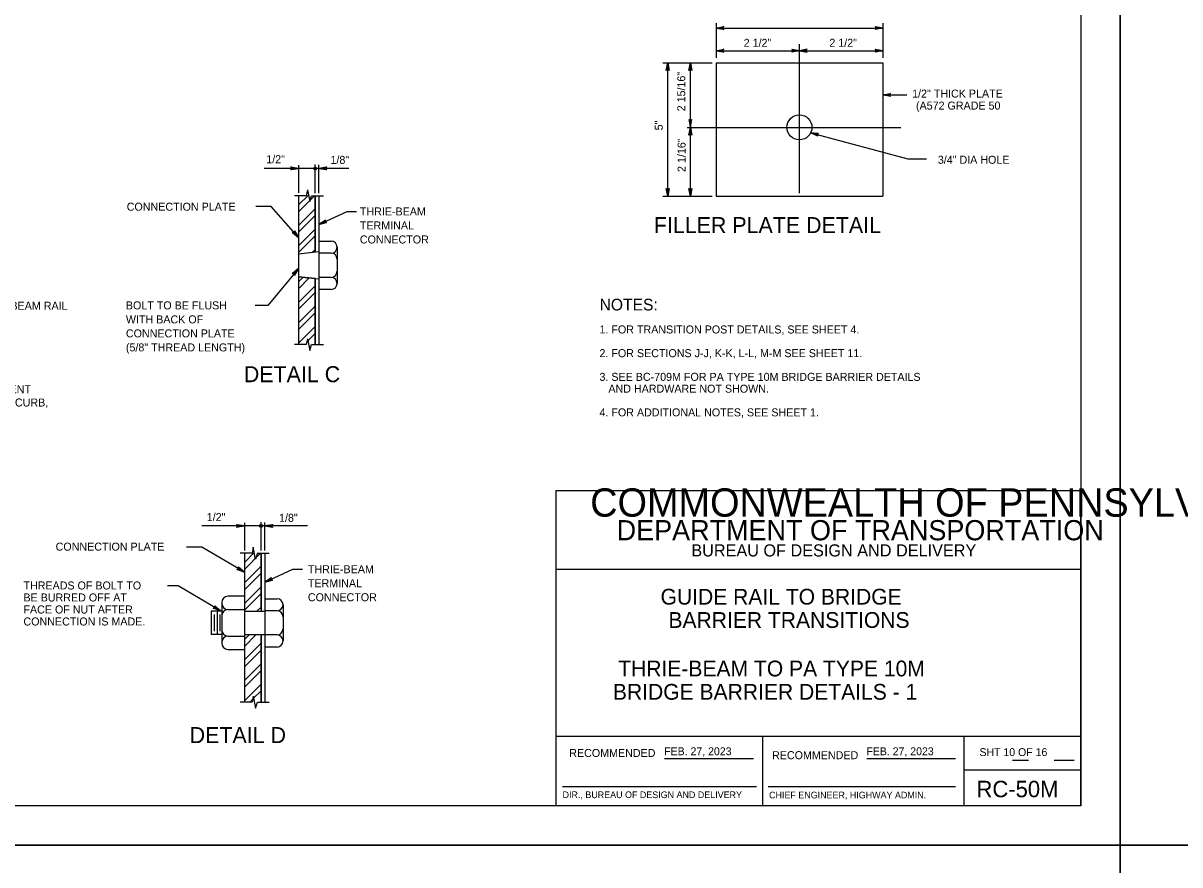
# Model space of a CAD drawing. Extents: x 632007860 to 635435983, y 295418622 to 297794622.
# Drawn here: x 634113016 to 634553598, y 296599122 to 296919777 of the extents above; entities that cross this region are included whole.
import ezdxf

# ---------------------------------------------------------------- set-up
doc = ezdxf.new("R2010")
doc.units = 0
for name, color, linetype in [('1', 7, 'Continuous'), ('2', 7, 'Continuous'), ('8', 7, 'Continuous'), ('PLT-BNDY', 7, 'Continuous'), ('S-DETL-DIMS', 7, 'Continuous'), ('S-DETL-T120', 7, 'Continuous'), ('S-DETL-T175', 7, 'Continuous'), ('S-DETL-T240', 7, 'Continuous'), ('S-PATT-WT01', 7, 'Continuous'), ('S-STEL', 7, 'Continuous')]:
    doc.layers.add(name, color=color, linetype=linetype)

msp = doc.modelspace()

# ---------------------------------------------------------------- linework, layer by layer
at = {"layer": '1'}
for p, q in [((634515860, 297185622), (634515860, 296621622)), ((634515860, 296741622), (634315860, 296741622)), ((634315860, 296741622), (634315860, 296621622)), ((634515860, 296621622), (634515860, 296741622)), ((634515860, 296711622), (634315860, 296711622)), ((634515860, 296647981), (634315860, 296647981)), ((634394661, 296647981), (634394661, 296621622)), ((634471362, 296647981), (634471362, 296621622)), ((634357325, 296639611), (634391211, 296639611)), ((634434323, 296639611), (634468193, 296639611)), ((634489803, 296638991), (634495945, 296638991)), ((634505683, 296638991), (634513329, 296638991)), ((634471362, 296635300), (634515860, 296635300)), ((634318485, 296628918), (634392385, 296628918)), ((634396791, 296628918), (634468131, 296628918)), ((634515860, 296621622), (633729860, 296621622))]:
    msp.add_line(p, q, dxfattribs=at)
at = {"layer": '8'}
for p, q in [((634408710, 296854982), (634408710, 296911744)), ((634365884, 296880076), (634447316, 296880076)), ((634224238, 296854043), (634224238, 296832606)), ((634224238, 296822469), (634224238, 296797306))]:
    msp.add_line(p, q, dxfattribs=at)
at = {"layer": 'PLT-BNDY'}
for points in [[(633689860, 297200622), (634530860, 297200622), (634530860, 296606622), (633689860, 296606622)], [(634530860, 297200622), (635371860, 297200622), (635371860, 296606622), (634530860, 296606622)], [(633689860, 296606622), (634530860, 296606622), (634530860, 296012622), (633689860, 296012622)], [(634530860, 296606622), (635371860, 296606622), (635371860, 296012622), (634530860, 296012622)]]:
    msp.add_lwpolyline(points, close=True, dxfattribs=at)
at = {"layer": 'S-DETL-DIMS'}
for p, q in [((634376959, 296919777), (634376959, 296906595)), ((634376959, 296917916), (634440460, 296917916)), ((634440460, 296919777), (634440460, 296906595)), ((634376959, 296909283), (634440460, 296909283)), ((634356686, 296904689), (634375430, 296904689)), ((634358547, 296853878), (634358547, 296904689)), ((634367180, 296853878), (634367180, 296904689)), ((634440460, 296892421), (634449661, 296892421)), ((634412998, 296878006), (634450005, 296868034)), ((634225704, 296864448), (634204882, 296864448)), ((634217882, 296865684), (634217882, 296855108)), ((634224238, 296855042), (634224238, 296865884)), ((634225704, 296855042), (634225704, 296865817)), ((634237068, 296864448), (634225704, 296864448)), ((634450005, 296868034), (634457063, 296868034)), ((634221271, 296856305), (634220807, 296854043)), ((634221271, 296856305), (634222171, 296851776)), ((634220807, 296854043), (634216318, 296854043)), ((634222171, 296851776), (634222851, 296854043)), ((634222851, 296854043), (634227378, 296854043)), ((634356686, 296853878), (634375430, 296853878)), ((634221271, 296799568), (634220807, 296797306)), ((634221271, 296799568), (634222171, 296795039)), ((634220807, 296797306), (634216318, 296797306)), ((634222171, 296795039), (634222851, 296797306)), ((634222851, 296797306), (634227378, 296797306)), ((634205098, 296728229), (634181069, 296728229)), ((634197277, 296729465), (634197277, 296718889)), ((634203632, 296718823), (634203632, 296729665)), ((634205098, 296718823), (634205098, 296729598)), ((634221315, 296728229), (634205098, 296728229)), ((634200665, 296720086), (634200202, 296717824)), ((634201565, 296715557), (634200665, 296720086)), ((634200202, 296717824), (634195712, 296717824)), ((634202245, 296717824), (634201565, 296715557)), ((634202245, 296717824), (634206772, 296717824)), ((634200665, 296663349), (634200202, 296661087)), ((634200665, 296663349), (634201565, 296658820)), ((634200202, 296661087), (634195712, 296661087)), ((634201565, 296658820), (634202245, 296661087)), ((634202245, 296661087), (634206772, 296661087))]:
    msp.add_line(p, q, dxfattribs=at)
for points in [[(634376959, 296917916), (634379919, 296918470), (634379690, 296918312), (634379573, 296918114), (634379539, 296917916), (634379573, 296917717), (634379690, 296917519), (634379919, 296917361), (634376959, 296917916), (634379690, 296917519), (634379573, 296917717), (634376959, 296917916), (634379539, 296917916), (634379573, 296918114), (634376959, 296917916), (634379690, 296918312)], [(634440460, 296917916), (634437501, 296917361), (634437729, 296917519), (634437846, 296917717), (634437880, 296917916), (634437846, 296918114), (634437729, 296918312), (634437501, 296918470), (634440460, 296917916), (634437729, 296918312), (634437846, 296918114), (634440460, 296917916), (634437880, 296917916), (634437846, 296917717), (634440460, 296917916), (634437729, 296917519)], [(634376959, 296909283), (634379919, 296909837), (634379690, 296909679), (634379573, 296909481), (634379539, 296909283), (634379573, 296909084), (634379690, 296908886), (634379919, 296908728), (634376959, 296909283), (634379690, 296908886), (634379573, 296909084), (634376959, 296909283), (634379539, 296909283), (634379573, 296909481), (634376959, 296909283), (634379690, 296909679)], [(634408710, 296909283), (634405750, 296908728), (634405978, 296908886), (634406096, 296909084), (634406130, 296909283), (634406096, 296909481), (634405978, 296909679), (634405750, 296909837), (634408710, 296909283), (634405978, 296909679), (634406096, 296909481), (634408710, 296909283), (634406130, 296909283), (634406096, 296909084), (634408710, 296909283), (634405978, 296908886)], [(634408710, 296909283), (634411669, 296908728), (634411441, 296908886), (634411323, 296909084), (634411289, 296909283), (634411323, 296909481), (634411441, 296909679), (634411669, 296909837), (634408710, 296909283), (634411441, 296909679), (634411323, 296909481), (634408710, 296909283), (634411289, 296909283), (634411323, 296909084), (634408710, 296909283), (634411441, 296908886)], [(634440460, 296909283), (634437501, 296908728), (634437729, 296908886), (634437846, 296909084), (634437880, 296909283), (634437846, 296909481), (634437729, 296909679), (634437501, 296909837), (634440460, 296909283), (634437729, 296909679), (634437846, 296909481), (634440460, 296909283), (634437880, 296909283), (634437846, 296909084), (634440460, 296909283), (634437729, 296908886)], [(634358547, 296904689), (634359102, 296901729), (634358944, 296901957), (634358746, 296902075), (634358547, 296902109), (634358349, 296902075), (634358150, 296901957), (634357992, 296901729), (634358547, 296904689), (634358150, 296901957), (634358349, 296902075), (634358547, 296904689), (634358547, 296902109), (634358746, 296902075), (634358547, 296904689), (634358944, 296901957)], [(634367180, 296904689), (634367735, 296901729), (634367577, 296901957), (634367379, 296902075), (634367180, 296902109), (634366982, 296902075), (634366783, 296901957), (634366625, 296901729), (634367180, 296904689), (634366783, 296901957), (634366982, 296902075), (634367180, 296904689), (634367180, 296902109), (634367379, 296902075), (634367180, 296904689), (634367577, 296901957)], [(634440460, 296892421), (634443419, 296892976), (634443191, 296892818), (634443074, 296892619), (634443040, 296892421), (634443074, 296892222), (634443191, 296892024), (634443419, 296891866), (634440460, 296892421), (634443191, 296892024), (634443074, 296892222), (634440460, 296892421), (634443040, 296892421), (634443074, 296892619), (634440460, 296892421), (634443191, 296892818)], [(634367180, 296880076), (634367735, 296883035), (634367577, 296882807), (634367379, 296882690), (634367180, 296882656), (634366982, 296882690), (634366783, 296882807), (634366625, 296883035), (634367180, 296880076), (634366783, 296882807), (634366982, 296882690), (634367180, 296880076), (634367180, 296882656), (634367379, 296882690), (634367180, 296880076), (634367577, 296882807)], [(634367180, 296880076), (634367735, 296877117), (634367577, 296877345), (634367379, 296877462), (634367180, 296877496), (634366982, 296877462), (634366783, 296877345), (634366625, 296877117), (634367180, 296880076), (634366783, 296877345), (634366982, 296877462), (634367180, 296880076), (634367180, 296877496), (634367379, 296877462), (634367180, 296880076), (634367577, 296877345)], [(634412998, 296878006), (634416000, 296877771), (634415870, 296877725), (634415739, 296877678), (634415656, 296877598), (634415574, 296877517), (634415531, 296877426), (634415489, 296877334), (634415480, 296877234), (634415470, 296877134), (634415501, 296877023), (634415532, 296876912), (634415622, 296876806), (634415711, 296876700), (634412998, 296878006), (634415622, 296876806), (634415532, 296876912), (634412998, 296878006), (634415501, 296877023), (634415470, 296877134), (634412998, 296878006), (634415480, 296877234), (634415489, 296877334), (634412998, 296878006), (634415531, 296877426), (634415574, 296877517), (634412998, 296878006), (634415656, 296877598), (634415739, 296877678), (634412998, 296878006), (634415870, 296877725)], [(634217882, 296864448), (634214923, 296863893), (634215037, 296863972), (634215151, 296864051), (634215210, 296864151), (634215269, 296864250), (634215286, 296864349), (634215303, 296864448), (634215286, 296864547), (634215269, 296864647), (634215210, 296864746), (634215151, 296864845), (634215037, 296864924), (634214923, 296865003), (634217882, 296864448), (634215037, 296864924), (634215151, 296864845), (634217882, 296864448), (634215210, 296864746), (634215269, 296864647), (634217882, 296864448), (634215286, 296864547), (634215303, 296864448), (634217882, 296864448), (634215286, 296864349), (634215269, 296864250), (634217882, 296864448), (634215210, 296864151), (634215151, 296864051), (634217882, 296864448), (634215037, 296863972)], [(634225704, 296864448), (634228663, 296865003), (634228549, 296864924), (634228435, 296864845), (634228377, 296864746), (634228318, 296864647), (634228301, 296864547), (634228284, 296864448), (634228301, 296864349), (634228318, 296864250), (634228377, 296864151), (634228435, 296864051), (634228549, 296863972), (634228663, 296863893), (634225704, 296864448), (634228549, 296863972), (634228435, 296864051), (634225704, 296864448), (634228377, 296864151), (634228318, 296864250), (634225704, 296864448), (634228301, 296864349), (634228284, 296864448), (634225704, 296864448), (634228301, 296864547), (634228318, 296864647), (634225704, 296864448), (634228377, 296864746), (634228435, 296864845), (634225704, 296864448), (634228549, 296864924)], [(634358547, 296853878), (634357992, 296856837), (634358150, 296856609), (634358349, 296856492), (634358547, 296856458), (634358746, 296856492), (634358944, 296856609), (634359102, 296856837), (634358547, 296853878), (634358944, 296856609), (634358746, 296856492), (634358547, 296853878), (634358547, 296856458), (634358349, 296856492), (634358547, 296853878), (634358150, 296856609)], [(634367180, 296853878), (634366625, 296856837), (634366783, 296856609), (634366982, 296856492), (634367180, 296856458), (634367379, 296856492), (634367577, 296856609), (634367735, 296856837), (634367180, 296853878), (634367577, 296856609), (634367379, 296856492), (634367180, 296853878), (634367180, 296856458), (634366982, 296856492), (634367180, 296853878), (634366783, 296856609)], [(634217882, 296838130), (634207457, 296849897), (634201605, 296849897)], [(634225704, 296843087), (634236381, 296848043), (634239983, 296848043)], [(634225704, 296843087), (634228155, 296844836), (634228084, 296844716), (634228014, 296844597), (634228003, 296844482), (634227991, 296844367), (634228017, 296844270), (634228044, 296844173), (634228101, 296844090), (634228158, 296844007), (634228253, 296843942), (634228348, 296843877), (634228485, 296843853), (634228622, 296843829), (634225704, 296843087), (634228485, 296843853), (634228348, 296843877), (634225704, 296843087), (634228253, 296843942), (634228158, 296844007), (634225704, 296843087), (634228101, 296844090), (634228044, 296844173), (634225704, 296843087), (634228017, 296844270), (634227991, 296844367), (634225704, 296843087), (634228003, 296844482), (634228014, 296844597), (634225704, 296843087), (634228084, 296844716)], [(634217882, 296838130), (634215505, 296839977), (634215639, 296839944), (634215774, 296839911), (634215887, 296839933), (634216001, 296839955), (634216086, 296840008), (634216172, 296840061), (634216235, 296840139), (634216298, 296840218), (634216333, 296840328), (634216368, 296840437), (634216352, 296840575), (634216335, 296840713), (634217882, 296838130), (634216352, 296840575), (634216368, 296840437), (634217882, 296838130), (634216333, 296840328), (634216298, 296840218), (634217882, 296838130), (634216235, 296840139), (634216172, 296840061), (634217882, 296838130), (634216086, 296840008), (634216001, 296839955), (634217882, 296838130), (634215887, 296839933), (634215774, 296839911), (634217882, 296838130), (634215639, 296839944)], [(634217882, 296826245), (634206216, 296812202), (634201444, 296812202)], [(634217882, 296826245), (634216371, 296823641), (634216386, 296823779), (634216400, 296823917), (634216364, 296824026), (634216327, 296824135), (634216263, 296824213), (634216199, 296824291), (634216112, 296824343), (634216026, 296824394), (634215913, 296824415), (634215799, 296824435), (634215665, 296824400), (634215531, 296824365), (634217882, 296826245), (634215665, 296824400), (634215799, 296824435), (634217882, 296826245), (634215913, 296824415), (634216026, 296824394), (634217882, 296826245), (634216112, 296824343), (634216199, 296824291), (634217882, 296826245), (634216263, 296824213), (634216327, 296824135), (634217882, 296826245), (634216364, 296824026), (634216400, 296823917), (634217882, 296826245), (634216386, 296823779)], [(634197277, 296728229), (634194317, 296727674), (634194431, 296727753), (634194545, 296727832), (634194604, 296727932), (634194663, 296728031), (634194680, 296728130), (634194697, 296728229), (634194680, 296728328), (634194663, 296728428), (634194604, 296728527), (634194545, 296728626), (634194431, 296728705), (634194317, 296728784), (634197277, 296728229), (634194431, 296728705), (634194545, 296728626), (634197277, 296728229), (634194604, 296728527), (634194663, 296728428), (634197277, 296728229), (634194680, 296728328), (634194697, 296728229), (634197277, 296728229), (634194680, 296728130), (634194663, 296728031), (634197277, 296728229), (634194604, 296727932), (634194545, 296727832), (634197277, 296728229), (634194431, 296727753)], [(634205098, 296728229), (634208058, 296728784), (634207944, 296728705), (634207830, 296728626), (634207771, 296728527), (634207712, 296728428), (634207695, 296728328), (634207678, 296728229), (634207695, 296728130), (634207712, 296728031), (634207771, 296727932), (634207830, 296727832), (634207944, 296727753), (634208058, 296727674), (634205098, 296728229), (634207944, 296727753), (634207830, 296727832), (634205098, 296728229), (634207771, 296727932), (634207712, 296728031), (634205098, 296728229), (634207695, 296728130), (634207678, 296728229), (634205098, 296728229), (634207695, 296728328), (634207712, 296728428), (634205098, 296728229), (634207771, 296728527), (634207830, 296728626), (634205098, 296728229), (634207944, 296728705)], [(634197277, 296710652), (634181108, 296720161), (634175255, 296720161)], [(634197277, 296710652), (634194444, 296711674), (634194583, 296711685), (634194721, 296711695), (634194822, 296711751), (634194923, 296711806), (634194988, 296711883), (634195053, 296711960), (634195089, 296712054), (634195124, 296712148), (634195124, 296712264), (634195123, 296712379), (634195065, 296712505), (634195007, 296712631), (634197277, 296710652), (634195065, 296712505), (634195123, 296712379), (634197277, 296710652), (634195124, 296712264), (634195124, 296712148), (634197277, 296710652), (634195089, 296712054), (634195053, 296711960), (634197277, 296710652), (634194988, 296711883), (634194923, 296711806), (634197277, 296710652), (634194822, 296711751), (634194721, 296711695), (634197277, 296710652), (634194583, 296711685)], [(634205098, 296706868), (634215775, 296711825), (634219377, 296711825)], [(634205098, 296706868), (634207549, 296708617), (634207478, 296708497), (634207408, 296708378), (634207397, 296708263), (634207385, 296708148), (634207412, 296708051), (634207438, 296707954), (634207495, 296707871), (634207552, 296707788), (634207647, 296707723), (634207743, 296707658), (634207879, 296707634), (634208016, 296707611), (634205098, 296706868), (634207879, 296707634), (634207743, 296707658), (634205098, 296706868), (634207647, 296707723), (634207552, 296707788), (634205098, 296706868), (634207495, 296707871), (634207438, 296707954), (634205098, 296706868), (634207412, 296708051), (634207385, 296708148), (634205098, 296706868), (634207397, 296708263), (634207408, 296708378), (634205098, 296706868), (634207478, 296708497)], [(634188252, 296695858), (634172083, 296705367), (634168035, 296705367)], [(634188252, 296695858), (634185420, 296696880), (634185558, 296696890), (634185696, 296696900), (634185797, 296696956), (634185898, 296697012), (634185963, 296697089), (634186028, 296697166), (634186064, 296697260), (634186099, 296697354), (634186099, 296697469), (634186099, 296697585), (634186041, 296697711), (634185982, 296697836), (634188252, 296695858), (634186041, 296697711), (634186099, 296697585), (634188252, 296695858), (634186099, 296697469), (634186099, 296697354), (634188252, 296695858), (634186064, 296697260), (634186028, 296697166), (634188252, 296695858), (634185963, 296697089), (634185898, 296697012), (634188252, 296695858), (634185797, 296696956), (634185696, 296696900), (634188252, 296695858), (634185558, 296696890)]]:
    msp.add_lwpolyline(points, dxfattribs=at)
for centre, radius in [((634224238, 296864448), 529), ((634224238, 296864448), 265), ((634203632, 296728229), 529), ((634203632, 296728229), 265)]:
    msp.add_circle(centre, radius, dxfattribs=at)
at = {"layer": 'S-PATT-WT01'}
for p, q in [((634217882, 296850513), (634221670, 296854300)), ((634217882, 296847920), (634224005, 296854043)), ((634217882, 296842735), (634224238, 296849090)), ((634217882, 296840143), (634224238, 296846498)), ((634217882, 296834958), (634224238, 296841313)), ((634217882, 296832365), (634224238, 296838720)), ((634223199, 296832497), (634224238, 296833535)), ((634217882, 296821169), (634219663, 296822950)), ((634217882, 296818577), (634222009, 296822703)), ((634217882, 296813392), (634224238, 296819747)), ((634217882, 296810799), (634224238, 296817154)), ((634217882, 296805614), (634224238, 296811969)), ((634217882, 296803022), (634224238, 296809377)), ((634217882, 296797837), (634224238, 296804192)), ((634221426, 296798788), (634224238, 296801599)), ((634197277, 296714294), (634201064, 296718081)), ((634197277, 296711701), (634203399, 296717824)), ((634197277, 296706516), (634203632, 296712871)), ((634197277, 296703924), (634203632, 296710279)), ((634197277, 296698738), (634203632, 296705094)), ((634197277, 296696146), (634203632, 296702501)), ((634202034, 296695718), (634203632, 296697316)), ((634197277, 296684950), (634199245, 296686918)), ((634197277, 296682358), (634201837, 296686918)), ((634197277, 296677173), (634203632, 296683528)), ((634197277, 296674580), (634203632, 296680935)), ((634197277, 296669395), (634203632, 296675750)), ((634197277, 296666803), (634203632, 296673158)), ((634197277, 296661618), (634203632, 296667973)), ((634199339, 296661087), (634200424, 296662173)), ((634200820, 296662569), (634203632, 296665380))]:
    msp.add_line(p, q, dxfattribs=at)
at = {"layer": 'S-STEL'}
for p, q in [((634376959, 296904689), (634440460, 296904689)), ((634376959, 296904689), (634376959, 296853878)), ((634440460, 296904689), (634440460, 296853878)), ((634217882, 296854043), (634217882, 296797306)), ((634217882, 296854043), (634217882, 296831937)), ((634224238, 296832606), (634224238, 296854043)), ((634225704, 296854043), (634225704, 296832760)), ((634376959, 296853878), (634440460, 296853878)), ((634225704, 296836745), (634225704, 296818329)), ((634225704, 296836745), (634225704, 296836745)), ((634225704, 296836745), (634230315, 296836745)), ((634232613, 296834447), (634232613, 296820628)), ((634217882, 296831937), (634225704, 296832760)), ((634217882, 296831937), (634224238, 296832606)), ((634230315, 296832141), (634225704, 296832141)), ((634217882, 296823138), (634225704, 296822314)), ((634224238, 296822469), (634217882, 296823138)), ((634217882, 296823138), (634217882, 296797306)), ((634224238, 296797306), (634224238, 296822469)), ((634230315, 296822933), (634225704, 296822933)), ((634225704, 296822314), (634225704, 296797306)), ((634225704, 296818329), (634225704, 296818329)), ((634230315, 296818329), (634225704, 296818329)), ((634197277, 296717824), (634197277, 296661087)), ((634197277, 296717824), (634197277, 296695718)), ((634203632, 296717824), (634203632, 296695718)), ((634203632, 296696387), (634203632, 296717824)), ((634205098, 296717824), (634205098, 296695718)), ((634197277, 296701447), (634190999, 296701447)), ((634188701, 296698919), (634188701, 296683718)), ((634205098, 296700526), (634205098, 296682110)), ((634205098, 296700526), (634205098, 296700526)), ((634205098, 296700526), (634209710, 296700526)), ((634212008, 296698228), (634212008, 296684409)), ((634188701, 296695718), (634184688, 296695718)), ((634184688, 296695718), (634184688, 296686918)), ((634185779, 296694511), (634185779, 296688118)), ((634186871, 296695710), (634186871, 296686918)), ((634187962, 296694511), (634187962, 296688118)), ((634190999, 296696382), (634197277, 296696382)), ((634197277, 296695718), (634205098, 296695718)), ((634209710, 296695922), (634205098, 296695922)), ((634188701, 296686918), (634184688, 296686918)), ((634190999, 296686254), (634197277, 296686254)), ((634197277, 296686918), (634205098, 296686918)), ((634197277, 296686918), (634197277, 296661087)), ((634203632, 296686918), (634203632, 296661087)), ((634203632, 296661087), (634203632, 296686250)), ((634205098, 296686918), (634205098, 296661087)), ((634209710, 296686714), (634205098, 296686714)), ((634190999, 296681189), (634197277, 296681189)), ((634205098, 296682110), (634205098, 296682110)), ((634209710, 296682110), (634205098, 296682110))]:
    msp.add_line(p, q, dxfattribs=at)
msp.add_circle((634408710, 296880076), 4763, dxfattribs=at)
for centre, start, end in [((634230315, 296834447), 0, 90), ((634230315, 296834439), 270, 0), ((634230315, 296829843), 0, 90), ((634230315, 296825232), 270, 0), ((634230315, 296820635), 0, 90), ((634230315, 296820628), 270, 0), ((634209710, 296698228), 0, 90), ((634209710, 296698220), 270, 0), ((634209710, 296693624), 0, 90), ((634209710, 296689013), 270, 0), ((634209710, 296684416), 0, 90), ((634209710, 296684409), 270, 0)]:
    msp.add_arc(centre, 2298, start, end, dxfattribs=at)
for centre, start_param, end_param in [((634190999, 296698919), 3.1415927, 4.712389), ((634190999, 296698911), 4.712389, 6.2831853), ((634190999, 296693854), 3.1415927, 4.712389), ((634190999, 296688782), 4.712389, 6.2831853), ((634190999, 296683726), 3.1415927, 4.712389), ((634190999, 296683718), 4.712389, 6.2831853)]:
    msp.add_ellipse(centre, major_axis=(0, -2528), ratio=0.9090909, start_param=start_param, end_param=end_param, dxfattribs=at)

# ---------------------------------------------------------------- texts
at = {"layer": '1'}
for s, height, p in [('COMMONWEALTH OF PENNSYLVANIA', 10783.37, (634329011, 296731766)), ('DEPARTMENT OF TRANSPORTATION', 7684.29, (634339072, 296722771)), ('BUREAU OF DESIGN AND DELIVERY', 4622.09, (634367520, 296716609)), ('RECOMMENDED', 3048, (634321023, 296640216)), ('FEB. 27, 2023', 3000, (634357186, 296640887)), ('RECOMMENDED', 3048, (634398267, 296639379)), ('FEB. 27, 2023', 3000, (634434184, 296640887)), ('SHT 10 OF 16', 3000, (634477259, 296640576)), ('APPROVED', 19.2, (634358883, 296639554)), ('RC-50M', 6267.5, (634476143, 296624882)), ('DIR., BUREAU OF DESIGN AND DELIVERY', 2540, (634318485, 296624554)), ('CHIEF ENGINEER, HIGHWAY ADMIN.', 2540, (634397144, 296624445))]:
    msp.add_text(s, height=height, dxfattribs=at).set_placement(p)
at = {"layer": '2'}
for s, p in [('GUIDE RAIL TO BRIDGE', (634355804, 296698276)), ('BARRIER TRANSITIONS', (634358804, 296689401)), ('THRIE-BEAM TO PA TYPE 10M', (634339665, 296670927)), ('BRIDGE BARRIER DETAILS - 1', (634337657, 296662044))]:
    msp.add_text(s, height=6000, dxfattribs=at).set_placement(p)
at = {"layer": 'S-DETL-T120'}
for s, height, p in [('2 1/2"', 3048.1, (634387460, 296910748)), ('2 1/2"', 3048.1, (634420093, 296910771)), ('1/2" THICK PLATE', 3048, (634451629, 296891411)), ('(A572 GRADE 50', 3048, (634453093, 296886839)), (' 1/2"', 3048, (634204489, 296866410)), (' 1/8"', 3048, (634228949, 296866167)), ('3/4" DIA HOLE', 3048, (634461419, 296866203)), ('CONNECTION PLATE', 3048.01, (634152471, 296848319)), ('THRIE-BEAM ', 3048.01, (634241272, 296846511)), ('TERMINAL', 3048, (634241272, 296841177)), ('CONNECTOR', 3048, (634241272, 296835843)), ('   THRIE-BEAM RAIL', 3048.01, (634091212, 296810592)), ('BOLT TO BE FLUSH', 3048.01, (634152155, 296810728)), ('WITH BACK OF ', 3048.01, (634152155, 296805394)), ('CONNECTION PLATE', 3048.01, (634152155, 296800060)), ('(5/8" THREAD LENGTH)', 3048.01, (634152155, 296794726)), ('PLAIN CEMENT', 3048.01, (634085884, 296778813)), ('CONCRETE CURB,', 3048.01, (634085884, 296773732)), (' 1/2"', 3048, (634181815, 296730102)), (' 1/8"', 3048, (634209354, 296729812)), ('CONNECTION PLATE', 3048.01, (634125387, 296718824)), ('THRIE-BEAM ', 3048.01, (634221477, 296710219)), ('THREADS OF BOLT TO ', 3048.01, (634113133, 296704030)), ('TERMINAL', 3048, (634221477, 296704885)), ('BE BURRED OFF AT ', 3048.01, (634113133, 296699458)), ('CONNECTOR', 3048, (634221477, 296699551)), ('FACE OF NUT AFTER ', 3048.01, (634113133, 296694886)), ('CONNECTION IS MADE.', 3048.01, (634113133, 296690314))]:
    msp.add_text(s, height=height, dxfattribs=at).set_placement(p)
for s, height, rotation, p in [('2 15/16"', 3048.1, 90, (634365219, 296886170)), ('5"', 3048.1, 90, (634356642, 296878936)), ('2 1/16"', 3048.1, 90, (634365336, 296863078)), ('1. FOR TRANSITION POST DETAILS, SEE SHEET 4.', 3048.06, 360, (634332539, 296801554)), ('2. FOR SECTIONS J-J, K-K, L-L, M-M SEE SHEET 11.', 3048.06, 360, (634332539, 296792530)), ('3. SEE BC-709M FOR PA TYPE 10M BRIDGE BARRIER DETAILS', 3048.06, 360, (634332539, 296783505)), ('   AND HARDWARE NOT SHOWN.', 3048.06, 360, (634332539, 296778993)), ('4. FOR ADDITIONAL NOTES, SEE SHEET 1.', 3048.06, 360, (634332539, 296769969))]:
    msp.add_text(s, height=height, rotation=rotation, dxfattribs=at).set_placement(p)
at = {"layer": 'S-DETL-T175'}
msp.add_text('NOTES:', height=4450, dxfattribs=at).set_placement((634332581, 296810318))
at = {"layer": 'S-DETL-T240'}
for s, p in [('FILLER PLATE DETAIL', (634353241, 296839792)), ('DETAIL C', (634197076, 296782998)), ('DETAIL D', (634176437, 296645516))]:
    msp.add_text(s, height=6096, dxfattribs=at).set_placement(p)

doc.saveas('drawing.dxf')
